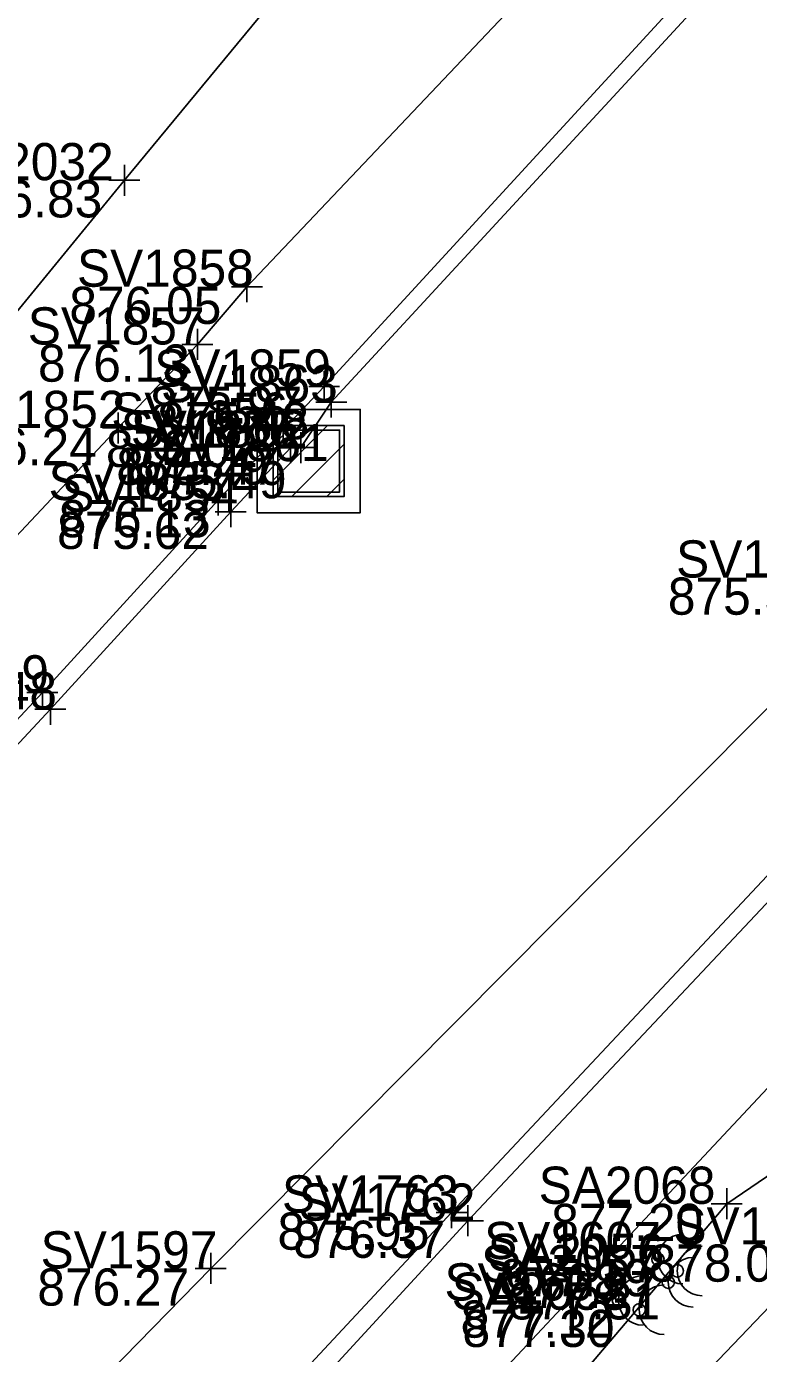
# Model space of a CAD drawing. Extents: x 1480001 to 1480402, y 379235 to 379603.
# Drawn here: x 1480114.39 to 1480138.03, y 379347.34 to 379390.17 of the extents above; entities that cross this region are included whole.
import ezdxf

# ---------------------------------------------------------------- set-up
doc = ezdxf.new("R2010")
doc.units = 0
for name, color, linetype in [('DR_X_Cells', 7, 'Continuous'), ('GK_Drainage_Nodes', 7, 'Continuous'), ('PV_X_Curb', 7, 'Continuous'), ('PV_X_Walk', 7, 'Continuous'), ('SV_X_Break_Lines', 7, 'Continuous'), ('SV_X_Shot_Marker', 7, 'Continuous'), ('SV_X_Text_Elevation', 7, 'Continuous'), ('SV_X_Text_Name', 7, 'Continuous'), ('UT_X_Misc_Cells', 7, 'Continuous'), ('UT_X_Water', 7, 'Continuous')]:
    doc.layers.add(name, color=color, linetype=linetype)

msp = doc.modelspace()

# ---------------------------------------------------------------- linework, layer by layer
at = {"layer": 'DR_X_Cells'}
for p, q in [((1480122.358, 379375.529), (1480124.117, 379377.288)), ((1480122.358, 379376.66), (1480122.986, 379377.288)), ((1480122.957, 379374.996), (1480124.65, 379376.689)), ((1480124.088, 379374.996), (1480124.65, 379375.558))]:
    msp.add_line(p, q, dxfattribs=at)
for points in [[(1480121.837, 379377.809), (1480125.171, 379377.809), (1480125.171, 379374.475), (1480121.837, 379374.475)], [(1480122.358, 379377.288), (1480124.65, 379377.288), (1480124.65, 379374.996), (1480122.358, 379374.996)], [(1480122.504, 379377.142), (1480124.504, 379377.142), (1480124.504, 379375.142), (1480122.504, 379375.142)]]:
    msp.add_lwpolyline(points, close=True, dxfattribs=at)
at = {"layer": 'GK_Drainage_Nodes'}
for p, q in [((1480123.504, 379377.809), (1480123.504, 379377.809)), ((1480123.504, 379377.142), (1480123.504, 379377.142)), ((1480122.504, 379376.142), (1480122.504, 379376.142)), ((1480123.504, 379376.142), (1480123.504, 379376.142)), ((1480123.504, 379376.142), (1480123.504, 379376.142)), ((1480123.504, 379376.142), (1480123.504, 379376.142)), ((1480124.504, 379376.142), (1480124.504, 379376.142)), ((1480123.504, 379375.142), (1480123.504, 379375.142)), ((1480123.504, 379374.475), (1480123.504, 379374.475))]:
    msp.add_line(p, q, dxfattribs=at)
at = {"layer": 'PV_X_Curb'}
for points in [[(1480097.622, 379349.287), (1480115.163, 379368.135), (1480120.989, 379374.507), (1480122.913, 379376.573), (1480123.248, 379376.579), (1480124.233, 379378.045), (1480138.666, 379393.676), (1480140.342, 379395.44), (1480142.173, 379398.797), (1480143.522, 379402.786), (1480144.219, 379407.995), (1480144.4, 379409.609), (1480144.536, 379411.589), (1480144.804, 379414.142), (1480144.365, 379416.981), (1480143.824, 379419.476), (1480142.93, 379422.24), (1480141.664, 379424.24), (1480139.564, 379427.9), (1480137.133, 379430.292), (1480135.19, 379432.332), (1480118.45, 379448.16)], [(1480097.272, 379349.731), (1480114.906, 379368.678), (1480120.582, 379374.885), (1480122.682, 379377.153), (1480124.005, 379378.548), (1480138.475, 379394.29), (1480139.717, 379395.951), (1480141.648, 379398.861), (1480143.063, 379403.22), (1480143.762, 379408.065), (1480143.873, 379409.698), (1480144.124, 379411.499), (1480144.338, 379414.245), (1480144.085, 379416.674), (1480143.405, 379419.529), (1480142.307, 379421.83), (1480141.33, 379424.009), (1480139.247, 379427.506), (1480136.787, 379429.98), (1480135, 379431.897), (1480118.039, 379447.914)], [(1480155.238, 379379.795), (1480153.548, 379379.014), (1480146.824, 379371.927), (1480145.567, 379370.605), (1480143.964, 379368.78), (1480128.12, 379351.892), (1480112.56, 379335.214), (1480098.785, 379320.255), (1480094.793, 379316.092), (1480093.124, 379314.172), (1480085.166, 379305.624), (1480081.585, 379301.702), (1480079.854, 379299.882), (1480067.172, 379286.11), (1480056.531, 379274.485), (1480055.169, 379272.969)], [(1480155.431, 379379.884), (1480153.98, 379378.667), (1480147.216, 379371.505), (1480146.047, 379370.27), (1480144.119, 379368.047), (1480128.647, 379351.629), (1480112.741, 379334.357), (1480099.146, 379319.858), (1480095.569, 379316.008), (1480093.53, 379313.846), (1480085.356, 379305.01), (1480081.967, 379301.397), (1480080.218, 379299.413), (1480067.589, 379285.613), (1480056.688, 379273.774), (1480055.547, 379272.623)]]:
    msp.add_lwpolyline(points, dxfattribs=at)
at = {"layer": 'PV_X_Walk'}
for points in [[(1480035.484, 379289.224), (1480050.568, 379305.437), (1480062.335, 379317.896), (1480064.038, 379319.719), (1480070.805, 379327.066), (1480078.054, 379334.946), (1480079.953, 379336.866), (1480094.208, 379352.393), (1480112.048, 379371.575), (1480117.348, 379377.211), (1480119.911, 379379.906), (1480121.511, 379381.77), (1480134.604, 379395.58), (1480136.695, 379398.148), (1480138.778, 379401.149), (1480140.004, 379404.725), (1480140.577, 379408.06), (1480140.982, 379411.311), (1480140.871, 379414.584), (1480140.225, 379417.636), (1480139.184, 379419.586), (1480133.124, 379425.845), (1480132.903, 379425.968), (1480114.834, 379442.96)], [(1480059.793, 379271.54), (1480075.261, 379288.048), (1480088.444, 379302.419), (1480096.088, 379310.695), (1480098.33, 379313.163), (1480111.975, 379327.613), (1480128.977, 379345.933), (1480145.46, 379363.52), (1480153.413, 379372.021), (1480155.772, 379374.786), (1480158.213, 379377.107), (1480160.137, 379378.801), (1480161.631, 379379.994)]]:
    msp.add_lwpolyline(points, dxfattribs=at)
at = {"layer": 'SV_X_Break_Lines'}
for points in [[(1480102.555, 379367.391), (1480110.126, 379376.156), (1480117.553, 379385.207), (1480124.442, 379393.548)], [(1480109.136, 379300.654), (1480103.503, 379307.396), (1480120.541, 379324.578), (1480124.787, 379337.805), (1480137.007, 379352.173), (1480144.932, 379357.565), (1480149.611, 379361.971), (1480150.052, 379364.189), (1480148.777, 379365.458), (1480163.875, 379379.601), (1480168.818, 379380.654), (1480172.802, 379381.332), (1480178.472, 379378.317), (1480184.655, 379372.421), (1480187.645, 379366.317)], [(1480184.481, 379363.392), (1480180.224, 379367.084), (1480176.21, 379371.695), (1480171.222, 379375.535), (1480168.077, 379375.239), (1480160.326, 379371.415), (1480150.91, 379361.854), (1480140.301, 379350.86), (1480130.798, 379340.93), (1480121.664, 379330.001), (1480112.679, 379319.616)]]:
    msp.add_lwpolyline(points, dxfattribs=at)
at = {"layer": 'SV_X_Shot_Marker'}
for p, q in [((1480117.553, 379385.707), (1480117.553, 379384.707)), ((1480117.053, 379385.207), (1480118.053, 379385.207)), ((1480117.553, 379385.207), (1480117.553, 379385.207)), ((1480121.511, 379382.27), (1480121.511, 379381.27)), ((1480121.011, 379381.77), (1480122.011, 379381.77)), ((1480121.511, 379381.77), (1480121.511, 379381.77)), ((1480119.911, 379380.406), (1480119.911, 379379.406)), ((1480119.411, 379379.906), (1480120.411, 379379.906)), ((1480119.911, 379379.906), (1480119.911, 379379.906)), ((1480124.005, 379379.048), (1480124.005, 379378.048)), ((1480123.505, 379378.548), (1480124.505, 379378.548)), ((1480124.005, 379378.548), (1480124.005, 379378.548)), ((1480124.233, 379378.545), (1480124.233, 379377.545)), ((1480123.733, 379378.045), (1480124.733, 379378.045)), ((1480124.233, 379378.045), (1480124.233, 379378.045)), ((1480117.348, 379377.711), (1480117.348, 379376.711)), ((1480122.682, 379377.653), (1480122.682, 379376.653)), ((1480116.848, 379377.211), (1480117.848, 379377.211)), ((1480117.348, 379377.211), (1480117.348, 379377.211)), ((1480122.182, 379377.153), (1480123.182, 379377.153)), ((1480122.682, 379377.153), (1480122.682, 379377.153)), ((1480122.913, 379377.073), (1480122.913, 379376.073)), ((1480123.248, 379377.079), (1480123.248, 379376.079)), ((1480122.413, 379376.573), (1480123.413, 379376.573)), ((1480122.748, 379376.579), (1480123.748, 379376.579)), ((1480122.913, 379376.573), (1480122.913, 379376.573)), ((1480123.248, 379376.579), (1480123.248, 379376.579)), ((1480120.582, 379375.385), (1480120.582, 379374.385)), ((1480120.082, 379374.885), (1480121.082, 379374.885)), ((1480120.582, 379374.885), (1480120.582, 379374.885)), ((1480120.989, 379375.007), (1480120.989, 379374.007)), ((1480120.489, 379374.507), (1480121.489, 379374.507)), ((1480120.989, 379374.507), (1480120.989, 379374.507)), ((1480114.906, 379369.178), (1480114.906, 379368.178)), ((1480114.406, 379368.678), (1480115.406, 379368.678)), ((1480114.906, 379368.678), (1480114.906, 379368.678)), ((1480115.163, 379368.635), (1480115.163, 379367.635)), ((1480114.663, 379368.135), (1480115.663, 379368.135)), ((1480115.163, 379368.135), (1480115.163, 379368.135)), ((1480137.007, 379352.673), (1480137.007, 379351.673)), ((1480128.12, 379352.392), (1480128.12, 379351.392)), ((1480128.647, 379352.129), (1480128.647, 379351.129)), ((1480136.507, 379352.173), (1480137.507, 379352.173)), ((1480137.007, 379352.173), (1480137.007, 379352.173)), ((1480127.62, 379351.892), (1480128.62, 379351.892)), ((1480128.12, 379351.892), (1480128.12, 379351.892)), ((1480128.147, 379351.629), (1480129.147, 379351.629)), ((1480128.647, 379351.629), (1480128.647, 379351.629)), ((1480120.344, 379350.587), (1480120.344, 379349.587)), ((1480119.844, 379350.087), (1480120.844, 379350.087)), ((1480120.344, 379350.087), (1480120.344, 379350.087))]:
    msp.add_line(p, q, dxfattribs=at)
at = {"layer": 'UT_X_Misc_Cells'}
for centre in [(1480134.784, 379350.389), (1480135.41, 379350.007), (1480135.119, 379349.641), (1480133.511, 379349.053), (1480134.181, 379348.753)]:
    msp.add_circle(centre, 0.2, dxfattribs=at)
for centre in [(1480135.584, 379350.389), (1480136.21, 379350.007), (1480135.919, 379349.641), (1480134.311, 379349.053), (1480134.981, 379348.753)]:
    msp.add_arc(centre, 0.8, 90, 270, dxfattribs=at)
at = {"layer": 'UT_X_Water'}
msp.add_lwpolyline([(1480169.204, 379397.823), (1480165.761, 379394.087), (1480162.59, 379391.88), (1480159.156, 379388.706), (1480148.911, 379378.819), (1480120.344, 379350.087), (1480106.297, 379335.736), (1480080.736, 379308.289), (1480073.091, 379299.637), (1480056.748, 379281.628), (1480051.266, 379275.974)], dxfattribs=at)

# ---------------------------------------------------------------- texts
at = {"layer": 'SV_X_Text_Elevation'}
for s, p in [('876.83', (1480111.931, 379384.007)), ('876.05', (1480115.776, 379380.57)), ('876.13', (1480114.762, 379378.706)), ('875.97', (1480118.383, 379377.348)), ('875.48', (1480118.611, 379376.845)), ('876.24', (1480111.755, 379376.011)), ('876.02', (1480116.956, 379375.953)), ('875.49', (1480117.291, 379375.373)), ('875.47', (1480117.636, 379375.379)), ('875.49', (1480117.882, 379374.942)), ('876.13', (1480115.433, 379373.685)), ('875.62', (1480115.377, 379373.307)), ('875.30', (1480135.105, 379371.185)), ('877.20', (1480131.338, 379350.973)), ('875.95', (1480122.498, 379350.692)), ('876.37', (1480123.006, 379350.429)), ('878.00', (1480134.481, 379349.66)), ('877.19', (1480129.664, 379349.189)), ('876.27', (1480114.741, 379348.887)), ('877.27', (1480129.845, 379348.807)), ('877.31', (1480129.95, 379348.441)), ('877.12', (1480128.41, 379347.853)), ('877.30', (1480128.474, 379347.553))]:
    msp.add_text(s, height=1.2, dxfattribs=at).set_placement(p)
at = {"layer": 'SV_X_Text_Name'}
for s, p in [('SV2032', (1480111.497, 379385.207)), ('SV1858', (1480116.022, 379381.77)), ('SV1857', (1480114.432, 379379.906)), ('SV1859', (1480118.516, 379378.548)), ('SV1863', (1480118.735, 379378.045)), ('SV1852', (1480111.878, 379377.211)), ('SV1856', (1480117.127, 379377.153)), ('SV1855', (1480117.434, 379376.573)), ('SV1862', (1480117.759, 379376.579)), ('SV1861', (1480118.44, 379376.142)), ('SV1853', (1480115.103, 379374.885)), ('SV1854', (1480115.519, 379374.507)), ('SV1757', (1480135.371, 379372.385)), ('SV1849', (1480109.408, 379368.678)), ('SV1848', (1480109.665, 379368.135)), ('SA2068', (1480130.932, 379352.173)), ('SV1763', (1480122.641, 379351.892)), ('SV1762', (1480123.177, 379351.629)), ('SV1818', (1480135.285, 379350.86)), ('SV1597', (1480114.846, 379350.087)), ('SV1607', (1480129.172, 379350.389)), ('SA2056', (1480129.288, 379350.007)), ('SA2057', (1480129.073, 379349.641)), ('SV1608', (1480127.89, 379349.053)), ('SA2058', (1480128.124, 379348.753))]:
    msp.add_text(s, height=1.2, dxfattribs=at).set_placement(p)

doc.saveas('drawing.dxf')
